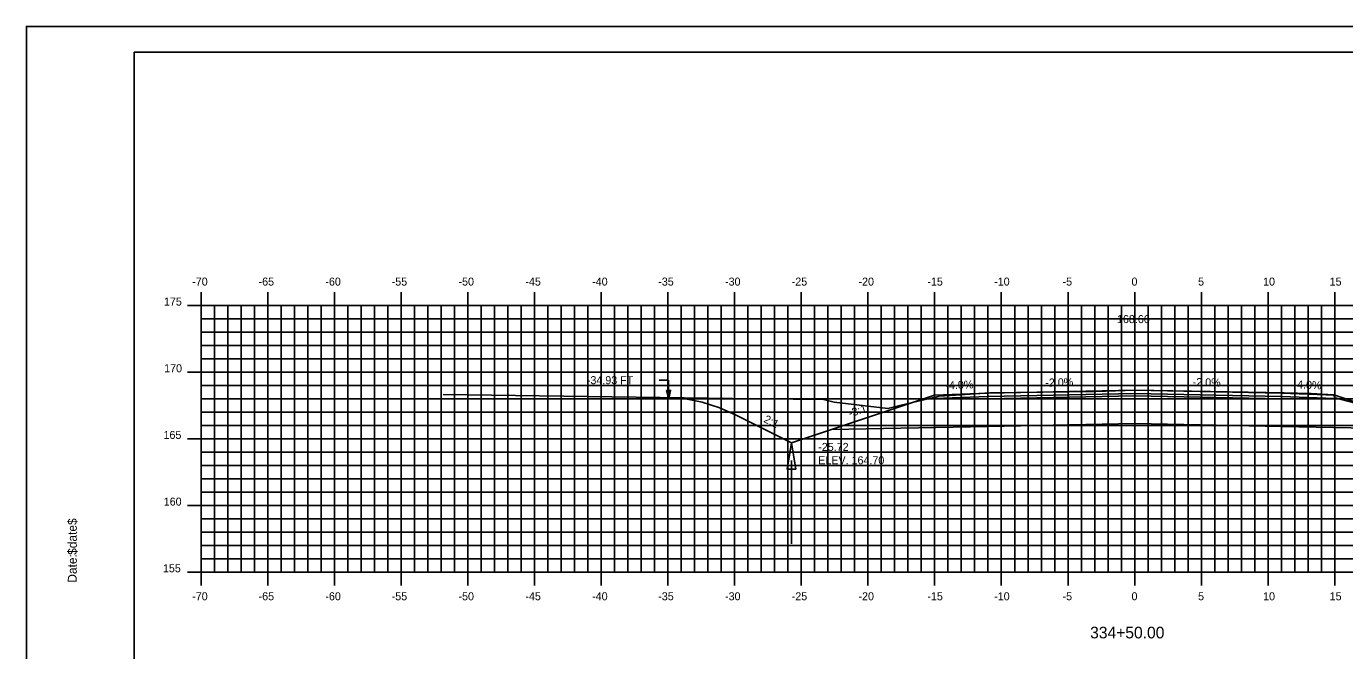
# Model space of a CAD drawing. Extents: x 1141868 to 1142038, y 608981 to 609091.
# Drawn here: x 1141867.7 to 1141966.5, y 609044.5 to 609091.3 of the extents above; entities that cross this region are included whole.
import ezdxf

# ---------------------------------------------------------------- set-up
doc = ezdxf.new("R2010")
doc.units = 0
for name, color, linetype in [('ANNOTATION', 7, 'Continuous'), ('BORDER', 7, 'Continuous'), ('D_Drainage_Ditch_Line', 7, 'Continuous'), ('D_Roadway_Centerline', 7, 'Continuous'), ('D_Roadway_Centerline_Text', 7, 'Continuous'), ('D_Roadway_Edge_Shoulder', 7, 'Continuous'), ('D_Roadway_Edge_TW', 7, 'Continuous'), ('D_Roadway_Pavement', 7, 'Continuous'), ('D_Roadway_SlopeLines', 7, 'Continuous'), ('D_Roadway_SubGrade', 7, 'Continuous'), ('D_Text_Standard', 7, 'Continuous'), ('H_V ANNOTATION', 7, 'Continuous'), ('MAJOR', 7, 'Continuous'), ('MINOR', 7, 'Continuous'), ('PLOT BOUNDARY', 7, 'Continuous'), ('S_Roadway_Centerline', 7, 'Continuous')]:
    doc.layers.add(name, color=color, linetype=linetype)

msp = doc.modelspace()

# ---------------------------------------------------------------- linework, layer by layer
msp.add_lwpolyline([(1141915.849, 609063.427), (1141917.099, 609063.333), (1141918.349, 609063.087), (1141919.599, 609062.69), (1141920.849, 609062.141), (1141925.059, 609060.036), (1141928.059, 609061.036), (1141935.783, 609063.61), (1141935.784, 609063.61), (1141939.784, 609063.77), (1141950.784, 609063.99), (1141961.784, 609063.77), (1141965.784, 609063.61), (1141973.507, 609061.036), (1141976.507, 609060.036), (1141979.667, 609061.616), (1141980.917, 609062.159), (1141982.167, 609062.54), (1141983.417, 609062.758), (1141984.667, 609062.813)])
at = {"layer": 'BORDER'}
msp.add_lwpolyline([(1141875.784, 608984.335), (1142035.784, 608984.335), (1142035.784, 609089.335), (1141875.784, 609089.335)], close=True, dxfattribs=at)
at = {"layer": 'D_Drainage_Ditch_Line'}
msp.add_line((1141925.059, 609058.724), (1141925.059, 609052.48), dxfattribs=at)
msp.add_lwpolyline([(1141925.387, 609058.067), (1141924.731, 609058.067), (1141925.059, 609060.036)], close=True, dxfattribs=at)
at = {"layer": 'D_Roadway_Edge_Shoulder'}
for points in [[(1141939.784, 609063.77), (1141935.784, 609063.61), (1141935.784, 609063.36), (1141939.784, 609063.52)], [(1141961.784, 609063.77), (1141965.784, 609063.61), (1141965.784, 609063.36), (1141961.784, 609063.52)]]:
    msp.add_lwpolyline(points, close=True, dxfattribs=at)
at = {"layer": 'D_Roadway_Edge_TW'}
msp.add_lwpolyline([(1141939.784, 609063.52), (1141939.784, 609063.77), (1141950.784, 609063.99), (1141961.784, 609063.77), (1141961.784, 609063.52), (1141950.784, 609063.74)], close=True, dxfattribs=at)
at = {"layer": 'D_Roadway_Pavement'}
msp.add_lwpolyline([(1141939.784, 609063.354), (1141939.784, 609063.52), (1141950.784, 609063.74), (1141961.784, 609063.52), (1141961.784, 609063.354), (1141950.784, 609063.574)], close=True, dxfattribs=at)
at = {"layer": 'D_Roadway_SlopeLines'}
for points in [[(1141925.059, 609060.036), (1141920.849, 609062.141), (1141919.599, 609062.69), (1141918.349, 609063.087), (1141917.099, 609063.333), (1141915.849, 609063.427)], [(1141928.059, 609061.036), (1141925.059, 609060.036)]]:
    msp.add_lwpolyline(points, dxfattribs=at)
at = {"layer": 'D_Roadway_SubGrade'}
for points in [[(1141939.784, 609063.354), (1141939.784, 609063.52), (1141935.784, 609063.36), (1141935.784, 609063.61), (1141935.783, 609063.61), (1141928.059, 609061.036), (1141939.784, 609061.27)], [(1141939.784, 609061.27), (1141939.784, 609063.354), (1141950.784, 609063.574), (1141961.784, 609063.354), (1141961.784, 609061.27), (1141950.784, 609061.49)], [(1141961.784, 609063.354), (1141961.784, 609063.52), (1141965.784, 609063.36), (1141965.784, 609063.61), (1141965.784, 609063.61), (1141973.507, 609061.036), (1141961.784, 609061.27)]]:
    msp.add_lwpolyline(points, close=True, dxfattribs=at)
at = {"layer": 'D_Text_Standard'}
msp.add_lwpolyline([(1141915.849, 609063.391), (1141915.824, 609064.741), (1141915.144, 609064.741)], dxfattribs=at)
msp.add_lwpolyline([(1141915.849, 609063.391), (1141915.693, 609063.97), (1141915.984, 609063.976)], close=True, dxfattribs=at)
at = {"layer": 'MAJOR'}
for p, q in [((1141880.784, 609071.337), (1141880.784, 609070.335)), ((1141885.784, 609071.337), (1141885.784, 609070.335)), ((1141890.784, 609071.337), (1141890.784, 609070.335)), ((1141895.784, 609071.337), (1141895.784, 609070.335)), ((1141900.784, 609071.337), (1141900.784, 609070.335)), ((1141905.784, 609071.337), (1141905.784, 609070.335)), ((1141910.784, 609071.337), (1141910.784, 609070.335)), ((1141915.784, 609071.337), (1141915.784, 609070.335)), ((1141920.784, 609071.337), (1141920.784, 609070.335)), ((1141925.784, 609071.337), (1141925.784, 609070.335)), ((1141930.784, 609071.337), (1141930.784, 609070.335)), ((1141935.784, 609071.337), (1141935.784, 609070.335)), ((1141940.784, 609071.337), (1141940.784, 609070.335)), ((1141945.784, 609071.337), (1141945.784, 609070.335)), ((1141950.784, 609071.337), (1141950.784, 609070.335)), ((1141955.784, 609071.337), (1141955.784, 609070.335)), ((1141960.784, 609071.337), (1141960.784, 609070.335)), ((1141965.784, 609071.337), (1141965.784, 609070.335)), ((1141879.782, 609070.335), (1141880.784, 609070.335)), ((1141880.784, 609070.335), (1142020.784, 609070.335)), ((1141880.784, 609050.335), (1141880.784, 609070.335)), ((1141880.784, 609050.335), (1141880.784, 609070.335)), ((1141880.784, 609070.335), (1142020.784, 609070.335)), ((1141885.784, 609050.335), (1141885.784, 609070.335)), ((1141890.784, 609050.335), (1141890.784, 609070.335)), ((1141895.784, 609050.335), (1141895.784, 609070.335)), ((1141900.784, 609050.335), (1141900.784, 609070.335)), ((1141905.784, 609050.335), (1141905.784, 609070.335)), ((1141910.784, 609050.335), (1141910.784, 609070.335)), ((1141915.784, 609050.335), (1141915.784, 609070.335)), ((1141920.784, 609050.335), (1141920.784, 609070.335)), ((1141925.784, 609050.335), (1141925.784, 609070.335)), ((1141930.784, 609050.335), (1141930.784, 609070.335)), ((1141935.784, 609050.335), (1141935.784, 609070.335)), ((1141940.784, 609050.335), (1141940.784, 609070.335)), ((1141945.784, 609050.335), (1141945.784, 609070.335)), ((1141950.784, 609050.335), (1141950.784, 609070.335)), ((1141955.784, 609050.335), (1141955.784, 609070.335)), ((1141960.784, 609050.335), (1141960.784, 609070.335)), ((1141965.784, 609050.335), (1141965.784, 609070.335)), ((1141879.782, 609065.335), (1141880.784, 609065.335)), ((1141880.784, 609065.335), (1142020.784, 609065.335)), ((1141879.782, 609060.335), (1141880.784, 609060.335)), ((1141880.784, 609060.335), (1142020.784, 609060.335)), ((1141879.782, 609055.335), (1141880.784, 609055.335)), ((1141880.784, 609055.335), (1142020.784, 609055.335)), ((1141879.782, 609050.335), (1141880.784, 609050.335)), ((1141880.784, 609050.335), (1142020.784, 609050.335)), ((1141880.784, 609050.335), (1142020.784, 609050.335)), ((1141880.784, 609049.333), (1141880.784, 609050.335)), ((1141885.784, 609049.333), (1141885.784, 609050.335)), ((1141890.784, 609049.333), (1141890.784, 609050.335)), ((1141895.784, 609049.333), (1141895.784, 609050.335)), ((1141900.784, 609049.333), (1141900.784, 609050.335)), ((1141905.784, 609049.333), (1141905.784, 609050.335)), ((1141910.784, 609049.333), (1141910.784, 609050.335)), ((1141915.784, 609049.333), (1141915.784, 609050.335)), ((1141920.784, 609049.333), (1141920.784, 609050.335)), ((1141925.784, 609049.333), (1141925.784, 609050.335)), ((1141930.784, 609049.333), (1141930.784, 609050.335)), ((1141935.784, 609049.333), (1141935.784, 609050.335)), ((1141940.784, 609049.333), (1141940.784, 609050.335)), ((1141945.784, 609049.333), (1141945.784, 609050.335)), ((1141950.784, 609049.333), (1141950.784, 609050.335)), ((1141955.784, 609049.333), (1141955.784, 609050.335)), ((1141960.784, 609049.333), (1141960.784, 609050.335)), ((1141965.784, 609049.333), (1141965.784, 609050.335))]:
    msp.add_line(p, q, dxfattribs=at)
at = {"layer": 'MINOR'}
for p, q in [((1141881.784, 609050.335), (1141881.784, 609070.335)), ((1141882.784, 609050.335), (1141882.784, 609070.335)), ((1141883.784, 609050.335), (1141883.784, 609070.335)), ((1141884.784, 609050.335), (1141884.784, 609070.335)), ((1141886.784, 609050.335), (1141886.784, 609070.335)), ((1141887.784, 609050.335), (1141887.784, 609070.335)), ((1141888.784, 609050.335), (1141888.784, 609070.335)), ((1141889.784, 609050.335), (1141889.784, 609070.335)), ((1141891.784, 609050.335), (1141891.784, 609070.335)), ((1141892.784, 609050.335), (1141892.784, 609070.335)), ((1141893.784, 609050.335), (1141893.784, 609070.335)), ((1141894.784, 609050.335), (1141894.784, 609070.335)), ((1141896.784, 609050.335), (1141896.784, 609070.335)), ((1141897.784, 609050.335), (1141897.784, 609070.335)), ((1141898.784, 609050.335), (1141898.784, 609070.335)), ((1141899.784, 609050.335), (1141899.784, 609070.335)), ((1141901.784, 609050.335), (1141901.784, 609070.335)), ((1141902.784, 609050.335), (1141902.784, 609070.335)), ((1141903.784, 609050.335), (1141903.784, 609070.335)), ((1141904.784, 609050.335), (1141904.784, 609070.335)), ((1141906.784, 609050.335), (1141906.784, 609070.335)), ((1141907.784, 609050.335), (1141907.784, 609070.335)), ((1141908.784, 609050.335), (1141908.784, 609070.335)), ((1141909.784, 609050.335), (1141909.784, 609070.335)), ((1141911.784, 609050.335), (1141911.784, 609070.335)), ((1141912.784, 609050.335), (1141912.784, 609070.335)), ((1141913.784, 609050.335), (1141913.784, 609070.335)), ((1141914.784, 609050.335), (1141914.784, 609070.335)), ((1141916.784, 609050.335), (1141916.784, 609070.335)), ((1141917.784, 609050.335), (1141917.784, 609070.335)), ((1141918.784, 609050.335), (1141918.784, 609070.335)), ((1141919.784, 609050.335), (1141919.784, 609070.335)), ((1141921.784, 609050.335), (1141921.784, 609070.335)), ((1141922.784, 609050.335), (1141922.784, 609070.335)), ((1141923.784, 609050.335), (1141923.784, 609070.335)), ((1141924.784, 609050.335), (1141924.784, 609070.335)), ((1141926.784, 609050.335), (1141926.784, 609070.335)), ((1141927.784, 609050.335), (1141927.784, 609070.335)), ((1141928.784, 609050.335), (1141928.784, 609070.335)), ((1141929.784, 609050.335), (1141929.784, 609070.335)), ((1141931.784, 609050.335), (1141931.784, 609070.335)), ((1141932.784, 609050.335), (1141932.784, 609070.335)), ((1141933.784, 609050.335), (1141933.784, 609070.335)), ((1141934.784, 609050.335), (1141934.784, 609070.335)), ((1141936.784, 609050.335), (1141936.784, 609070.335)), ((1141937.784, 609050.335), (1141937.784, 609070.335)), ((1141938.784, 609050.335), (1141938.784, 609070.335)), ((1141939.784, 609050.335), (1141939.784, 609070.335)), ((1141941.784, 609050.335), (1141941.784, 609070.335)), ((1141942.784, 609050.335), (1141942.784, 609070.335)), ((1141943.784, 609050.335), (1141943.784, 609070.335)), ((1141944.784, 609050.335), (1141944.784, 609070.335)), ((1141946.784, 609050.335), (1141946.784, 609070.335)), ((1141947.784, 609050.335), (1141947.784, 609070.335)), ((1141948.784, 609050.335), (1141948.784, 609070.335)), ((1141949.784, 609050.335), (1141949.784, 609070.335)), ((1141951.784, 609050.335), (1141951.784, 609070.335)), ((1141952.784, 609050.335), (1141952.784, 609070.335)), ((1141953.784, 609050.335), (1141953.784, 609070.335)), ((1141954.784, 609050.335), (1141954.784, 609070.335)), ((1141956.784, 609050.335), (1141956.784, 609070.335)), ((1141957.784, 609050.335), (1141957.784, 609070.335)), ((1141958.784, 609050.335), (1141958.784, 609070.335)), ((1141959.784, 609050.335), (1141959.784, 609070.335)), ((1141961.784, 609050.335), (1141961.784, 609070.335)), ((1141962.784, 609050.335), (1141962.784, 609070.335)), ((1141963.784, 609050.335), (1141963.784, 609070.335)), ((1141964.784, 609050.335), (1141964.784, 609070.335)), ((1141880.784, 609069.335), (1142020.784, 609069.335)), ((1141880.784, 609069.335), (1141881.786, 609069.335)), ((1141880.784, 609068.335), (1142020.784, 609068.335)), ((1141880.784, 609068.335), (1141881.786, 609068.335)), ((1141880.784, 609067.335), (1142020.784, 609067.335)), ((1141880.784, 609067.335), (1141881.786, 609067.335)), ((1141880.784, 609066.335), (1142020.784, 609066.335)), ((1141880.784, 609066.335), (1141881.786, 609066.335)), ((1141880.784, 609064.335), (1142020.784, 609064.335)), ((1141880.784, 609064.335), (1141881.786, 609064.335)), ((1141880.784, 609063.335), (1142020.784, 609063.335)), ((1141880.784, 609063.335), (1141881.786, 609063.335)), ((1141880.784, 609062.335), (1142020.784, 609062.335)), ((1141880.784, 609062.335), (1141881.786, 609062.335)), ((1141880.784, 609061.335), (1142020.784, 609061.335)), ((1141880.784, 609061.335), (1141881.786, 609061.335)), ((1141880.784, 609059.335), (1142020.784, 609059.335)), ((1141880.784, 609059.335), (1141881.786, 609059.335)), ((1141880.784, 609058.335), (1142020.784, 609058.335)), ((1141880.784, 609058.335), (1141881.786, 609058.335)), ((1141880.784, 609057.335), (1142020.784, 609057.335)), ((1141880.784, 609057.335), (1141881.786, 609057.335)), ((1141880.784, 609056.335), (1142020.784, 609056.335)), ((1141880.784, 609056.335), (1141881.786, 609056.335)), ((1141880.784, 609054.335), (1142020.784, 609054.335)), ((1141880.784, 609054.335), (1141881.786, 609054.335)), ((1141880.784, 609053.335), (1142020.784, 609053.335)), ((1141880.784, 609053.335), (1141881.786, 609053.335)), ((1141880.784, 609052.335), (1142020.784, 609052.335)), ((1141880.784, 609052.335), (1141881.786, 609052.335)), ((1141880.784, 609051.335), (1142020.784, 609051.335)), ((1141880.784, 609051.335), (1141881.786, 609051.335))]:
    msp.add_line(p, q, dxfattribs=at)
at = {"layer": 'PLOT BOUNDARY'}
msp.add_lwpolyline([(1141867.691, 608981.276), (1142037.691, 608981.276), (1142037.691, 609091.276), (1141867.691, 609091.276)], close=True, dxfattribs=at)
at = {"layer": 'S_Roadway_Centerline'}
msp.add_lwpolyline([(1141898.931, 609063.67), (1141920.641, 609063.358), (1141927.442, 609063.286), (1141928.262, 609063.104), (1141932.279, 609062.607), (1141933.177, 609062.83), (1141936.132, 609063.548), (1141937.343, 609063.608), (1141939.921, 609063.8), (1141947.871, 609063.896), (1141950.814, 609063.993), (1141959.278, 609063.846), (1141962.001, 609063.801), (1141964.008, 609063.742), (1141965.696, 609063.641), (1141965.824, 609063.405), (1141969.332, 609062.485), (1141969.794, 609062.639), (1141971.337, 609062.56), (1141973.519, 609063.048), (1141987.101, 609062.762), (1142002.535, 609062.728)], dxfattribs=at)

# ---------------------------------------------------------------- texts
at = {"layer": 'ANNOTATION'}
for s, rotation, p in [('-4.0%', 2.29061, (1141936.6, 609064.044)), ('-2.0%', 1.14576, (1141944.087, 609064.257)), ('-2.0%', 358.85424, (1141955.127, 609064.304)), ('-4.0%', 357.70939, (1141962.68, 609064.135)), ('2:1', 333.43495, (1141922.921, 609061.623)), ('-3:1', 18.43482, (1141929.438, 609061.95))]:
    msp.add_text(s, height=0.6, rotation=rotation, dxfattribs=at).set_placement(p)
at = {"layer": 'BORDER'}
for s, p in [('$date$', (1141871.469, 609051.64)), ('Date:', (1141871.469, 609049.552))]:
    msp.add_text(s, height=0.6696, rotation=90, dxfattribs=at).set_placement(p)
at = {"layer": 'D_Roadway_Centerline'}
for s, p in [('C', (1141950.779, 609063.99)), ('L', (1141950.784, 609063.983))]:
    msp.add_text(s, height=0.0146, dxfattribs=at).set_placement(p)
at = {"layer": 'D_Roadway_Centerline_Text'}
msp.add_text('168.66', height=0.6, dxfattribs=at).set_placement((1141949.457, 609069.022))
at = {"layer": 'D_Text_Standard'}
for s, p in [('-34.93 FT', (1141909.711, 609064.441)), ('-25.72', (1141927.059, 609059.436)), ('ELEV. 164.70', (1141927.059, 609058.434))]:
    msp.add_text(s, height=0.6, dxfattribs=at).set_placement(p)
at = {"layer": 'H_V ANNOTATION'}
for s, height, p in [('-70', 0.6, (1141880.125, 609071.835)), ('-65', 0.6, (1141885.101, 609071.835)), ('-60', 0.6, (1141890.109, 609071.835)), ('-55', 0.6, (1141895.08, 609071.835)), ('-50', 0.6, (1141900.088, 609071.835)), ('-45', 0.6, (1141905.101, 609071.835)), ('-40', 0.6, (1141910.109, 609071.835)), ('-35', 0.6, (1141915.064, 609071.835)), ('-30', 0.6, (1141920.072, 609071.835)), ('-25', 0.6, (1141925.069, 609071.835)), ('-20', 0.6, (1141930.077, 609071.835)), ('-15', 0.6, (1141935.241, 609071.835)), ('-10', 0.6, (1141940.249, 609071.835)), ('-5', 0.6, (1141945.374, 609071.835)), ('0', 0.6, (1141950.543, 609071.835)), ('5', 0.6, (1141955.535, 609071.835)), ('10', 0.6, (1141960.409, 609071.835)), ('15', 0.6, (1141965.401, 609071.835)), ('175', 0.6, (1141878.005, 609070.335)), ('170', 0.6, (1141878.021, 609065.335)), ('165', 0.6, (1141877.973, 609060.335)), ('160', 0.6, (1141877.989, 609055.335)), ('155', 0.6, (1141877.93, 609050.335)), ('-70', 0.6, (1141880.125, 609048.235)), ('-65', 0.6, (1141885.101, 609048.235)), ('-60', 0.6, (1141890.109, 609048.235)), ('-55', 0.6, (1141895.08, 609048.235)), ('-50', 0.6, (1141900.088, 609048.235)), ('-45', 0.6, (1141905.101, 609048.235)), ('-40', 0.6, (1141910.109, 609048.235)), ('-35', 0.6, (1141915.064, 609048.235)), ('-30', 0.6, (1141920.072, 609048.235)), ('-25', 0.6, (1141925.069, 609048.235)), ('-20', 0.6, (1141930.077, 609048.235)), ('-15', 0.6, (1141935.241, 609048.235)), ('-10', 0.6, (1141940.249, 609048.235)), ('-5', 0.6, (1141945.374, 609048.235)), ('0', 0.6, (1141950.543, 609048.235)), ('5', 0.6, (1141955.535, 609048.235)), ('10', 0.6, (1141960.409, 609048.235)), ('15', 0.6, (1141965.401, 609048.235)), ('334+50.00', 0.875, (1141947.444, 609045.378))]:
    msp.add_text(s, height=height, dxfattribs=at).set_placement(p)
at = {"layer": 'MAJOR'}
msp.add_text('-', height=0.006, dxfattribs=at).set_placement((1141880.779, 609050.335))
at = {"layer": 'S_Roadway_Centerline'}
for s, p in [('C', (1141950.809, 609063.993)), ('L', (1141950.814, 609063.986))]:
    msp.add_text(s, height=0.0146, dxfattribs=at).set_placement(p)

doc.saveas('drawing.dxf')
